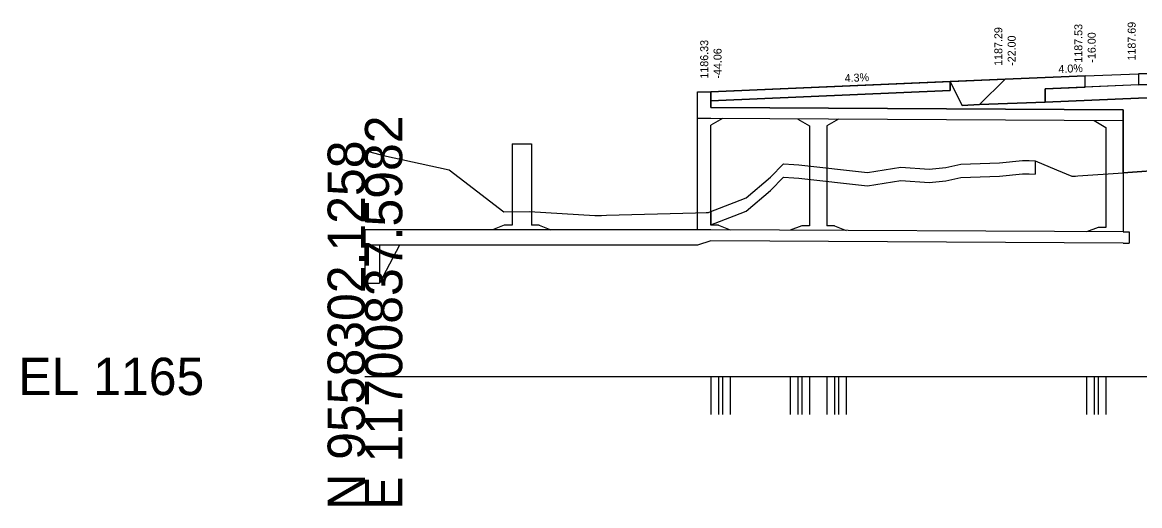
# Model space of a CAD drawing. Extents: x -75 to 1143, y -10 to 8583.
# Drawn here: x -25.7 to 58.1, y 4490.3 to 4526.6 of the extents above; entities that cross this region are included whole.
import ezdxf

# ---------------------------------------------------------------- set-up
doc = ezdxf.new("R2010")
doc.units = 0
for name, color, linetype in [('brgPreStructureNew', 7, 'Continuous'), ('Default', 7, 'Continuous'), ('Draft_XS_Grid', 7, 'Continuous'), ('dsnGeopakCellCrossSection', 7, 'Continuous'), ('dsnXSEarthwork', 7, 'Continuous'), ('dsnXsEarthworkShapesCF', 7, 'Continuous'), ('dsnXsEarthworkShapesUCSG', 7, 'Continuous'), ('dsnXsEarthworkShapesUCTP', 7, 'Continuous'), ('dsnXsExistingGround', 7, 'Continuous'), ('dsnXsExTsStripping', 7, 'Continuous'), ('dsnXsPCCPavement', 7, 'Continuous'), ('dsnXsShldrEarthFill', 7, 'Continuous'), ('dsnXsShldrGranular', 7, 'Continuous'), ('dsnXsShldrPCC', 7, 'Continuous'), ('dsnXsSideSlopes', 7, 'Continuous'), ('dsnXsSideSlopesDressing', 7, 'Continuous'), ('dsnXsSubbase', 7, 'Continuous'), ('dsnXsTextOffsetElevFinGrd', 7, 'Continuous'), ('dsnXsTextPavementSlope', 7, 'Continuous'), ('MIMIC_dsnXsExistingGround', 7, 'Continuous'), ('NONPLOT1', 7, 'Continuous')]:
    doc.layers.add(name, color=color, linetype=linetype)

msp = doc.modelspace()

# ---------------------------------------------------------------- linework, layer by layer
at = {"layer": 'brgPreStructureNew'}
for p, q in [((24.939, 4511), (24.939, 4521.33)), ((24.939, 4521.33), (25.943, 4521.33)), ((25.943, 4521.33), (25.943, 4520.17)), ((56.868, 4520), (25.943, 4520.17)), ((56.868, 4520), (56.868, 4510.83)), ((25.943, 4519.337), (24.939, 4519.337)), ((56.868, 4519.167), (25.943, 4519.337)), ((26.815, 4519.332), (25.943, 4518.837)), ((25.943, 4511.333), (25.943, 4518.837)), ((32.46, 4519.301), (33.332, 4518.796)), ((33.332, 4518.796), (33.332, 4511.293)), ((35.511, 4519.284), (34.639, 4518.789)), ((54.689, 4519.179), (55.561, 4518.674)), ((34.639, 4518.789), (34.639, 4511.286)), ((55.561, 4518.674), (55.561, 4511.171)), ((11.03, 4517.43), (12.483, 4517.43)), ((11.03, 4517.43), (11.03, 4511.333)), ((12.483, 4517.43), (12.483, 4511.333)), ((10.449, 4511.333), (9.577, 4511)), ((11.03, 4511.333), (10.449, 4511.333)), ((13.064, 4511.333), (12.483, 4511.333)), ((13.064, 4511.333), (13.936, 4511)), ((26.524, 4511.33), (25.943, 4511.333)), ((26.524, 4511.33), (27.396, 4510.992)), ((32.751, 4511.296), (31.879, 4510.967)), ((33.332, 4511.293), (32.751, 4511.296)), ((35.221, 4511.282), (34.639, 4511.286)), ((35.221, 4511.282), (36.092, 4510.944)), ((25.943, 4511), (0, 4511)), ((0, 4511), (0, 4507)), ((56.868, 4510.83), (25.943, 4511)), ((54.98, 4511.174), (54.108, 4510.845)), ((55.561, 4511.171), (54.98, 4511.174)), ((56.868, 4510.83), (57.304, 4510.83)), ((57.304, 4510.83), (57.304, 4509.997)), ((24.939, 4509.833), (0, 4509.833)), ((1.099, 4509.833), (1.099, 4507)), ((2.599, 4509.833), (1.099, 4507)), ((25.943, 4510.167), (24.939, 4509.833)), ((56.868, 4509.997), (25.943, 4510.167)), ((56.868, 4509.997), (57.304, 4509.997)), ((0, 4507), (1.099, 4507))]:
    msp.add_line(p, q, dxfattribs=at)
at = {"layer": 'dsnGeopakCellCrossSection'}
msp.add_line((0, 4500), (70, 4500), dxfattribs=at)
at = {"layer": 'dsnXSEarthwork'}
msp.add_lwpolyline([(48, 4522.288), (54, 4522.528), (58, 4522.688), (70, 4522.928), (82, 4522.688), (86, 4522.528), (92, 4522.288)], dxfattribs=at)
at = {"layer": 'dsnXsEarthworkShapesCF'}
for points in [[(63.803, 4515.761), (56.868, 4515.27), (56.868, 4520), (25.943, 4520.17), (25.944, 4520.663), (25.943, 4521.33), (43.889, 4522.11), (48, 4522.288), (54, 4522.528), (58, 4522.688), (70, 4522.928)], [(63.803, 4515.761), (56.868, 4515.27), (56.868, 4520), (25.943, 4520.17), (25.944, 4520.663), (43.889, 4521.443), (43.889, 4522.11), (44.781, 4520.326), (46.091, 4520.379), (51, 4520.575), (58, 4520.855), (70, 4521.095)]]:
    msp.add_lwpolyline(points, dxfattribs=at)
for points in [[(43.889, 4522.11), (48, 4522.288), (46.091, 4520.379), (44.781, 4520.326)], [(46.091, 4520.379), (51, 4520.575), (51, 4521.575), (54, 4521.695), (54, 4522.528), (48, 4522.288)], [(58, 4522.688), (58, 4521.855), (54, 4521.695), (54, 4522.528)], [(58, 4522.688), (58, 4521.855), (70, 4522.095), (82, 4521.855), (82, 4522.688), (70, 4522.928)], [(25.943, 4521.33), (25.944, 4520.663), (43.889, 4521.443), (43.889, 4522.11)], [(70, 4521.095), (82, 4520.855), (89, 4520.575), (89, 4521.575), (86, 4521.695), (82, 4521.855), (70, 4522.095), (58, 4521.855), (54, 4521.695), (51, 4521.575), (51, 4520.575), (58, 4520.855)]]:
    msp.add_lwpolyline(points, close=True, dxfattribs=at)
at = {"layer": 'dsnXsEarthworkShapesUCSG'}
for points in [[(63.803, 4515.761), (56.868, 4515.27), (56.868, 4520), (25.943, 4520.17), (25.944, 4520.663), (25.943, 4521.33), (43.889, 4522.11), (48, 4522.288), (54, 4522.528), (58, 4522.688), (70, 4522.928)], [(70, 4521.095), (58, 4520.855), (51, 4520.575), (46.091, 4520.379), (44.781, 4520.326), (43.889, 4522.11), (43.889, 4521.443), (25.944, 4520.663), (25.943, 4520.17), (56.868, 4520), (56.868, 4515.27), (63.803, 4515.761)]]:
    msp.add_lwpolyline(points, dxfattribs=at)
for points in [[(43.889, 4522.11), (48, 4522.288), (46.091, 4520.379), (44.781, 4520.326)], [(46.091, 4520.379), (51, 4520.575), (51, 4521.575), (54, 4521.695), (54, 4522.528), (48, 4522.288)], [(58, 4522.688), (58, 4521.855), (54, 4521.695), (54, 4522.528)], [(58, 4522.688), (58, 4521.855), (70, 4522.095), (82, 4521.855), (82, 4522.688), (70, 4522.928)], [(25.943, 4521.33), (25.944, 4520.663), (43.889, 4521.443), (43.889, 4522.11)], [(70, 4521.095), (82, 4520.855), (89, 4520.575), (89, 4521.575), (86, 4521.695), (82, 4521.855), (70, 4522.095), (58, 4521.855), (54, 4521.695), (51, 4521.575), (51, 4520.575), (58, 4520.855)]]:
    msp.add_lwpolyline(points, close=True, dxfattribs=at)
at = {"layer": 'dsnXsEarthworkShapesUCTP'}
for points in [[(63.803, 4515.761), (56.868, 4515.27), (56.868, 4520), (25.943, 4520.17), (25.944, 4520.663), (25.943, 4521.33), (43.889, 4522.11), (48, 4522.288), (54, 4522.528), (58, 4522.688), (70, 4522.928)], [(63.803, 4515.761), (56.868, 4515.27), (56.868, 4520), (25.943, 4520.17), (25.944, 4520.663), (43.889, 4521.443), (43.889, 4522.11), (44.781, 4520.326), (46.091, 4520.379), (51, 4520.575), (58, 4520.855), (70, 4521.095)]]:
    msp.add_lwpolyline(points, dxfattribs=at)
for points in [[(43.889, 4522.11), (44.781, 4520.326), (46.091, 4520.379), (48, 4522.288)], [(46.091, 4520.379), (51, 4520.575), (51, 4521.575), (54, 4521.695), (54, 4522.528), (48, 4522.288)], [(58, 4522.688), (58, 4521.855), (54, 4521.695), (54, 4522.528)], [(58, 4522.688), (58, 4521.855), (70, 4522.095), (82, 4521.855), (82, 4522.688), (70, 4522.928)], [(25.943, 4521.33), (25.944, 4520.663), (43.889, 4521.443), (43.889, 4522.11)], [(70, 4521.095), (82, 4520.855), (89, 4520.575), (89, 4521.575), (86, 4521.695), (82, 4521.855), (70, 4522.095), (58, 4521.855), (54, 4521.695), (51, 4521.575), (51, 4520.575), (58, 4520.855)]]:
    msp.add_lwpolyline(points, close=True, dxfattribs=at)
at = {"layer": 'dsnXsExistingGround'}
msp.add_lwpolyline([(25.943, 4521.33), (25.943, 4520.17), (56.868, 4520), (56.868, 4515.27), (63.803, 4515.761)], dxfattribs=at)
at = {"layer": 'dsnXsExTsStripping'}
for p, q in [((50.268, 4516.156), (50.268, 4515.156)), ((25.944, 4512.355), (25.944, 4511.355))]:
    msp.add_line(p, q, dxfattribs=at)
for points in [[(25.944, 4512.355), (27.695, 4513.045), (28.596, 4513.388), (30.412, 4514.94), (31.394, 4515.932), (32.153, 4515.881), (32.547, 4515.853), (37.7, 4515.302), (40.197, 4515.69), (42.317, 4515.536), (43.563, 4515.653), (44.699, 4515.911), (47.58, 4516.006), (49.305, 4516.189), (49.803, 4516.202), (50.268, 4516.156)], [(25.944, 4511.355), (27.695, 4512.045), (28.596, 4512.388), (30.412, 4513.94), (31.394, 4514.932), (32.153, 4514.881), (32.547, 4514.853), (37.7, 4514.302), (40.197, 4514.69), (42.317, 4514.536), (43.563, 4514.653), (44.699, 4514.911), (47.58, 4515.006), (49.305, 4515.189), (49.803, 4515.202), (50.268, 4515.156)]]:
    msp.add_lwpolyline(points, dxfattribs=at)
at = {"layer": 'dsnXsPCCPavement'}
msp.add_lwpolyline([(70, 4522.928), (58, 4522.688), (58, 4522.688), (58, 4521.855), (70, 4522.095), (70, 4522.095), (70, 4522.095), (82, 4521.855), (82, 4522.688), (82, 4522.688), (70, 4522.928), (70, 4522.928), (70, 4522.928)], dxfattribs=at)
at = {"layer": 'dsnXsShldrEarthFill'}
for p in [(43.889, 4522.11), (46.091, 4520.379)]:
    msp.add_line(p, (44.781, 4520.326), dxfattribs=at)
at = {"layer": 'dsnXsShldrGranular'}
msp.add_lwpolyline([(54, 4522.528), (48, 4522.288), (48, 4522.288), (46.091, 4520.379), (51, 4520.575), (51, 4520.575), (51, 4521.575), (51, 4521.575), (54, 4521.695), (54, 4521.695), (54, 4522.528), (54, 4522.528), (54, 4522.528)], dxfattribs=at)
at = {"layer": 'dsnXsShldrPCC'}
msp.add_lwpolyline([(58, 4522.688), (58, 4521.855), (54, 4521.695), (54, 4522.528), (58, 4522.688)], dxfattribs=at)
at = {"layer": 'dsnXsSideSlopes'}
msp.add_lwpolyline([(25.943, 4521.33), (25.943, 4521.33), (48, 4522.288)], dxfattribs=at)
at = {"layer": 'dsnXsSideSlopesDressing'}
for p, q in [((25.944, 4521.33), (25.944, 4520.663)), ((43.889, 4522.11), (43.889, 4521.443))]:
    msp.add_line(p, q, dxfattribs=at)
msp.add_lwpolyline([(25.944, 4520.663), (43.889, 4521.443)], dxfattribs=at)
at = {"layer": 'dsnXsSubbase'}
msp.add_lwpolyline([(51, 4521.575), (51, 4520.575), (58, 4520.855), (58, 4520.855), (70, 4521.095), (70, 4521.095), (70, 4521.095), (82, 4520.855), (82, 4520.855), (89, 4520.575), (89, 4521.575), (89, 4521.575), (82, 4521.855), (82, 4521.855), (70, 4522.095), (70, 4522.095), (70, 4522.095), (58, 4521.855), (58, 4521.855), (51, 4521.575), (51, 4521.575)], dxfattribs=at)
at = {"layer": 'MIMIC_dsnXsExistingGround'}
for points in [[(0, 4516.932), (1.393, 4516.554), (6.323, 4515.488), (7.055, 4514.908), (10.404, 4512.348), (12.339, 4512.373), (17.244, 4512.057), (17.742, 4512.069), (18.113, 4512.079), (24.799, 4512.256), (25.595, 4512.281), (25.665, 4512.28), (25.756, 4512.281), (25.943, 4512.355)], [(25.943, 4512.355), (27.695, 4513.045), (28.596, 4513.388), (30.412, 4514.94), (31.394, 4515.932), (32.153, 4515.881), (32.547, 4515.853), (37.7, 4515.302), (40.197, 4515.69), (42.317, 4515.536), (43.563, 4515.653), (44.699, 4515.911), (47.58, 4516.006), (49.305, 4516.189), (49.803, 4516.202), (50.268, 4516.156), (51.856, 4515.48), (53.005, 4515.018), (53.274, 4515.008), (53.471, 4515.029), (56.868, 4515.27)]]:
    msp.add_lwpolyline(points, dxfattribs=at)
at = {"layer": 'NONPLOT1'}
for p, q in [((25.943, 4500), (25.943, 4497.146)), ((26.524, 4500), (26.524, 4497.146)), ((26.815, 4500), (26.815, 4497.146)), ((27.396, 4500), (27.396, 4497.146)), ((31.879, 4500), (31.879, 4497.146)), ((32.46, 4500), (32.46, 4497.146)), ((32.751, 4500), (32.751, 4497.146)), ((33.332, 4500), (33.332, 4497.146)), ((34.639, 4500), (34.639, 4497.146)), ((35.221, 4500), (35.221, 4497.146)), ((35.511, 4500), (35.511, 4497.146)), ((36.092, 4500), (36.092, 4497.146)), ((54.108, 4500), (54.108, 4497.146)), ((54.689, 4500), (54.689, 4497.146)), ((54.98, 4500), (54.98, 4497.146)), ((55.561, 4500), (55.561, 4497.146))]:
    msp.add_line(p, q, dxfattribs=at)

# ---------------------------------------------------------------- texts
at = {"layer": 'Default'}
for p in [(47.996, 4522.284), (53.996, 4522.524), (57.996, 4522.684), (25.94, 4521.326), (57.996, 4520.851)]:
    msp.add_text('X', height=0.00781, dxfattribs=at).set_placement(p)
at = {"layer": 'Draft_XS_Grid'}
msp.add_text('-', height=0.0001, dxfattribs=at).set_placement((0, 4500))
at = {"layer": 'dsnGeopakCellCrossSection'}
for s, p in [('E 11700837.5982', (2.8, 4490)), ('N 9558302.1258', (0, 4490))]:
    msp.add_text(s, height=2.8, rotation=90, dxfattribs=at).set_placement(p)
msp.add_text('EL 1165', height=2.8, dxfattribs=at).set_placement((-26, 4498.6))
at = {"layer": 'dsnXsTextOffsetElevFinGrd'}
for s, p in [('1187.53', (53.8, 4523.528)), ('1187.69', (57.8, 4523.688)), ('1187.29', (47.8, 4523.288)), ('-22.00', (48.8, 4523.288)), ('-16.00', (54.8, 4523.528)), ('1186.33', (25.743, 4522.33)), ('-44.06', (26.743, 4522.33))]:
    msp.add_text(s, height=0.6, rotation=90, dxfattribs=at).set_placement(p)
at = {"layer": 'dsnXsTextPavementSlope'}
for s, rotation, p in [('4.0%', 2.29061, (52.018, 4522.749)), ('4.3%', 2.48721, (35.989, 4522.067))]:
    msp.add_text(s, height=0.6, rotation=rotation, dxfattribs=at).set_placement(p)

doc.saveas('drawing.dxf')
